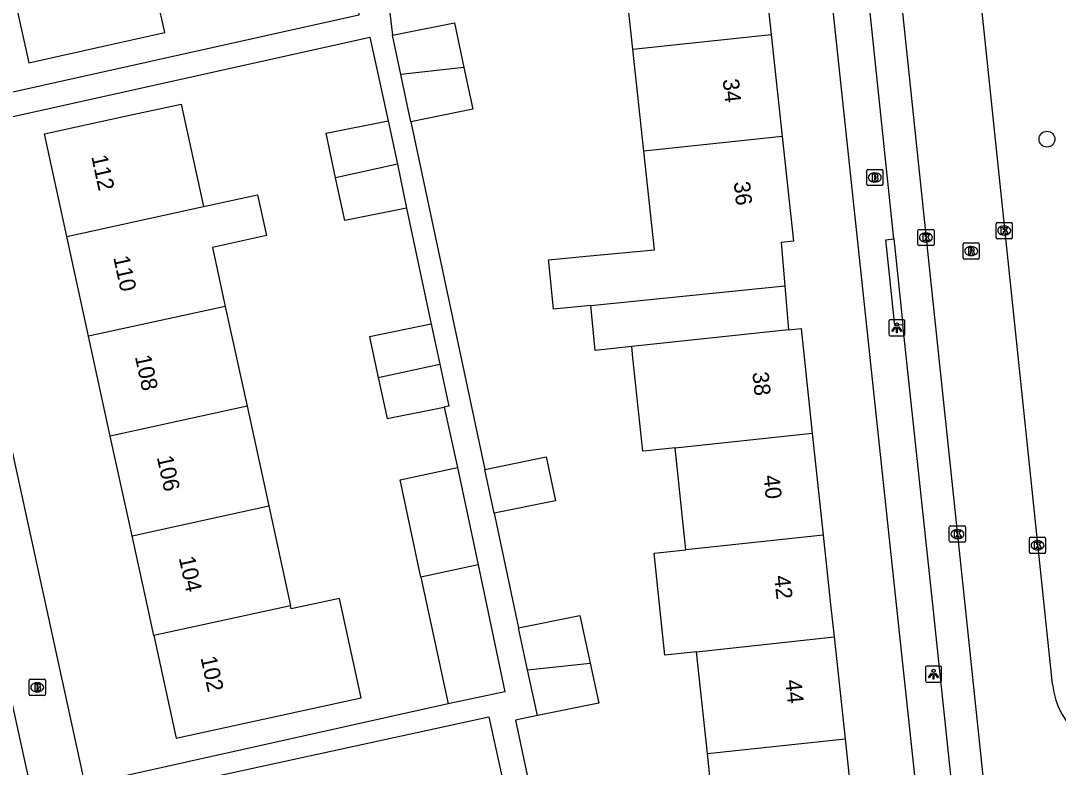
# Model space of a CAD drawing. Extents: x 160557 to 161245, y 385330 to 386505.
# Drawn here: x 160716.6 to 160780.6, y 385990 to 386036 of the extents above; entities that cross this region are included whole.
import ezdxf

# ---------------------------------------------------------------- set-up
doc = ezdxf.new("R2010")
doc.units = 0
for name, color, linetype in [('IMGEO_Boom', 7, 'Continuous'), ('IMGEO_Brandkraan', 7, 'Continuous'), ('IMGEO_Fietspad_gesloten', 7, 'Continuous'), ('IMGEO_Kolk', 7, 'Continuous'), ('IMGEO_Lichtpunt', 7, 'Continuous'), ('IMGEO_Pand', 7, 'Continuous'), ('IMGEO_Pand_nummerreeks', 7, 'Continuous'), ('IMGEO_Rijbaan_lokaal_open', 7, 'Continuous'), ('IMGEO_Rioolput', 7, 'Continuous'), ('IMGEO_Voetpad_open', 7, 'Continuous')]:
    doc.layers.add(name, color=color, linetype=linetype)

msp = doc.modelspace()

# ---------------------------------------------------------------- linework, layer by layer
at = {"layer": 'IMGEO_Boom'}
msp.add_circle((160779.939, 386028.694), 0.489, dxfattribs=at)
at = {"layer": 'IMGEO_Brandkraan'}
for p, q in [((160768.892, 386026.835), (160769.744, 386026.835)), ((160768.817, 386025.909), (160768.817, 386026.761)), ((160769.305, 386026.615), (160769.33, 386026.615)), ((160769.818, 386026.761), (160769.818, 386025.909)), ((160769.744, 386025.835), (160768.892, 386025.835)), ((160769.328, 386026.055), (160769.303, 386026.055)), ((160717.141, 385994.464), (160717.141, 385995.316)), ((160717.216, 385995.39), (160718.068, 385995.39)), ((160717.629, 385995.17), (160717.654, 385995.17)), ((160718.142, 385995.316), (160718.142, 385994.464)), ((160718.068, 385994.39), (160717.216, 385994.39)), ((160717.652, 385994.61), (160717.627, 385994.61))]:
    msp.add_line(p, q, dxfattribs=at)
for points in [[(160768.892, 386026.835), (160769.744, 386026.835)], [(160768.817, 386025.909), (160768.817, 386026.761)], [(160769.165, 386026.535), (160769.165, 386026.135), (160769.378, 386026.135)], [(160769.396, 386026.535), (160769.165, 386026.535)], [(160769.344, 386026.454), (160769.29, 386026.454), (160769.29, 386026.378)], [(160769.29, 386026.378), (160769.343, 386026.378)], [(160769.352, 386026.302), (160769.29, 386026.302), (160769.29, 386026.221)], [(160769.29, 386026.221), (160769.352, 386026.221)], [(160769.818, 386026.761), (160769.818, 386025.909)], [(160769.744, 386025.835), (160768.892, 386025.835)], [(160717.141, 385994.464), (160717.141, 385995.316)], [(160717.216, 385995.39), (160718.068, 385995.39)], [(160717.489, 385995.09), (160717.489, 385994.69), (160717.702, 385994.69)], [(160717.72, 385995.09), (160717.489, 385995.09)], [(160717.668, 385995.009), (160717.614, 385995.009), (160717.614, 385994.933)], [(160717.614, 385994.933), (160717.667, 385994.933)], [(160717.676, 385994.857), (160717.614, 385994.857), (160717.614, 385994.776)], [(160717.614, 385994.776), (160717.676, 385994.776)], [(160718.142, 385995.316), (160718.142, 385994.464)], [(160718.068, 385994.39), (160717.216, 385994.39)]]:
    msp.add_lwpolyline(points, dxfattribs=at)
for centre, radius, start, end in [((160768.894, 386026.759), 0.0765, 91.55205, 178.44795), ((160768.894, 386026.759), 0.0765, 91.55205, 178.44795), ((160769.742, 386026.759), 0.0765, 1.55205, 88.44795), ((160769.742, 386026.759), 0.0765, 1.55205, 88.44795), ((160769.345, 386026.416), 0.0379, 267.82845, 90.93552), ((160769.353, 386026.261), 0.0404, 269.87594, 90.50774), ((160769.384, 386026.386), 0.251, 268.66757, 293.53466), ((160769.4, 386026.39), 0.145, 59.4692, 91.53667), ((160769.425, 386026.437), 0.0922, 285.51372, 58.15012), ((160769.43, 386026.245), 0.105, 301.31148, 78.98903), ((160768.894, 386025.911), 0.0765, 181.55205, 268.44795), ((160768.894, 386025.911), 0.0765, 181.55205, 268.44795), ((160769.742, 386025.911), 0.0765, 271.55205, 358.44795), ((160769.742, 386025.911), 0.0765, 271.55205, 358.44795), ((160717.218, 385995.314), 0.0765, 91.55205, 178.44795), ((160717.218, 385995.314), 0.0765, 91.55205, 178.44795), ((160717.669, 385994.971), 0.0379, 267.82845, 90.93552), ((160717.677, 385994.816), 0.0404, 269.87594, 90.50774), ((160717.724, 385994.945), 0.145, 59.4692, 91.53667), ((160717.749, 385994.992), 0.0922, 285.51372, 58.15012), ((160717.754, 385994.8), 0.105, 301.31148, 78.98903), ((160718.066, 385995.314), 0.0765, 1.55205, 88.44795), ((160718.066, 385995.314), 0.0765, 1.55205, 88.44795), ((160717.218, 385994.466), 0.0765, 181.55205, 268.44795), ((160717.218, 385994.466), 0.0765, 181.55205, 268.44795), ((160717.708, 385994.941), 0.251, 268.66757, 293.53466), ((160718.066, 385994.466), 0.0765, 271.55205, 358.44795), ((160718.066, 385994.466), 0.0765, 271.55205, 358.44795)]:
    msp.add_arc(centre, radius, start, end, dxfattribs=at)
for centre, major_axis, ratio, start_param, end_param in [((160769.304, 386026.335), (-0.387, 0.002), 0.722429, 4.712389, 7.853982), ((160769.329, 386026.335), (-0.39, 0.002), 0.717154, 1.570796, 4.712389), ((160717.628, 385994.89), (-0.387, 0.002), 0.722429, 4.712389, 7.853982), ((160717.653, 385994.89), (-0.39, 0.002), 0.717154, 1.570796, 4.712389)]:
    msp.add_ellipse(centre, major_axis=major_axis, ratio=ratio, start_param=start_param, end_param=end_param, dxfattribs=at)
at = {"layer": 'IMGEO_Fietspad_gesloten'}
msp.add_lwpolyline([(160734.335, 385910.619), (160688.379, 386120.515), (160685.475, 386134.246), (160684.879, 386136.929)], dxfattribs=at)
at = {"layer": 'IMGEO_Kolk'}
for p, q in [((160771.972, 386022.203), (160771.972, 386023.055)), ((160772.047, 386023.129), (160772.899, 386023.129)), ((160772.973, 386023.055), (160772.973, 386022.203)), ((160776.803, 386022.632), (160776.803, 386023.484)), ((160776.878, 386023.558), (160777.73, 386023.558)), ((160777.291, 386023.338), (160777.316, 386023.338)), ((160777.804, 386023.484), (160777.804, 386022.632)), ((160772.483, 386022.349), (160772.458, 386022.349)), ((160772.46, 386022.909), (160772.485, 386022.909)), ((160777.73, 386022.558), (160776.878, 386022.558)), ((160777.314, 386022.778), (160777.289, 386022.778)), ((160772.899, 386022.129), (160772.047, 386022.129)), ((160773.917, 386003.915), (160773.917, 386004.767)), ((160773.992, 386004.841), (160774.844, 386004.841)), ((160774.405, 386004.621), (160774.43, 386004.621)), ((160774.918, 386004.767), (160774.918, 386003.915)), ((160774.844, 386003.841), (160773.992, 386003.841)), ((160774.428, 386004.061), (160774.403, 386004.061)), ((160778.859, 386003.22), (160778.859, 386004.072)), ((160778.934, 386004.146), (160779.786, 386004.146)), ((160779.347, 386003.926), (160779.372, 386003.926)), ((160779.86, 386004.072), (160779.86, 386003.22)), ((160779.786, 386003.146), (160778.934, 386003.146)), ((160779.37, 386003.366), (160779.345, 386003.366))]:
    msp.add_line(p, q, dxfattribs=at)
for points in [[(160771.972, 386022.203), (160771.972, 386023.055)], [(160772.047, 386023.129), (160772.899, 386023.129)], [(160772.973, 386023.055), (160772.973, 386022.203)], [(160776.803, 386022.632), (160776.803, 386023.484)], [(160776.878, 386023.558), (160777.73, 386023.558)], [(160777.124, 386023.258), (160777.247, 386023.258), (160777.247, 386023.107), (160777.377, 386023.258), (160777.541, 386023.258), (160777.395, 386023.107), (160777.548, 386022.858), (160777.396, 386022.858), (160777.311, 386023.022), (160777.247, 386022.955), (160777.247, 386022.858), (160777.124, 386022.858), (160777.124, 386023.258)], [(160777.804, 386023.484), (160777.804, 386022.632)], [(160772.293, 386022.829), (160772.416, 386022.829), (160772.416, 386022.678), (160772.546, 386022.829), (160772.71, 386022.829), (160772.564, 386022.678), (160772.717, 386022.429), (160772.565, 386022.429), (160772.48, 386022.593), (160772.416, 386022.526), (160772.416, 386022.429), (160772.293, 386022.429), (160772.293, 386022.829)], [(160777.73, 386022.558), (160776.878, 386022.558)], [(160772.899, 386022.129), (160772.047, 386022.129)], [(160773.917, 386003.915), (160773.917, 386004.767)], [(160773.992, 386004.841), (160774.844, 386004.841)], [(160774.238, 386004.541), (160774.361, 386004.541), (160774.361, 386004.39), (160774.491, 386004.541), (160774.655, 386004.541), (160774.509, 386004.39), (160774.662, 386004.141), (160774.51, 386004.141), (160774.425, 386004.305), (160774.361, 386004.238), (160774.361, 386004.141), (160774.238, 386004.141), (160774.238, 386004.541)], [(160774.918, 386004.767), (160774.918, 386003.915)], [(160774.844, 386003.841), (160773.992, 386003.841)], [(160778.859, 386003.22), (160778.859, 386004.072)], [(160778.934, 386004.146), (160779.786, 386004.146)], [(160779.18, 386003.846), (160779.303, 386003.846), (160779.303, 386003.695), (160779.433, 386003.846), (160779.597, 386003.846), (160779.451, 386003.695), (160779.604, 386003.446), (160779.452, 386003.446), (160779.367, 386003.61), (160779.303, 386003.543), (160779.303, 386003.446), (160779.18, 386003.446), (160779.18, 386003.846)], [(160779.86, 386004.072), (160779.86, 386003.22)], [(160779.786, 386003.146), (160778.934, 386003.146)]]:
    msp.add_lwpolyline(points, dxfattribs=at)
for centre, start, end in [((160772.049, 386023.053), 91.55205, 178.44795), ((160772.049, 386023.053), 91.55205, 178.44795), ((160772.897, 386023.053), 1.55205, 88.44795), ((160772.897, 386023.053), 1.55205, 88.44795), ((160776.88, 386023.482), 91.55205, 178.44795), ((160776.88, 386023.482), 91.55205, 178.44795), ((160777.728, 386023.482), 1.55205, 88.44795), ((160777.728, 386023.482), 1.55205, 88.44795), ((160776.88, 386022.634), 181.55205, 268.44795), ((160776.88, 386022.634), 181.55205, 268.44795), ((160777.728, 386022.634), 271.55205, 358.44795), ((160777.728, 386022.634), 271.55205, 358.44795), ((160772.049, 386022.205), 181.55205, 268.44795), ((160772.049, 386022.205), 181.55205, 268.44795), ((160772.897, 386022.205), 271.55205, 358.44795), ((160772.897, 386022.205), 271.55205, 358.44795), ((160773.994, 386004.765), 91.55205, 178.44795), ((160773.994, 386004.765), 91.55205, 178.44795), ((160774.842, 386004.765), 1.55205, 88.44795), ((160774.842, 386004.765), 1.55205, 88.44795), ((160773.994, 386003.917), 181.55205, 268.44795), ((160773.994, 386003.917), 181.55205, 268.44795), ((160774.842, 386003.917), 271.55205, 358.44795), ((160774.842, 386003.917), 271.55205, 358.44795), ((160778.936, 386004.07), 91.55205, 178.44795), ((160778.936, 386004.07), 91.55205, 178.44795), ((160779.784, 386004.07), 1.55205, 88.44795), ((160779.784, 386004.07), 1.55205, 88.44795), ((160778.936, 386003.222), 181.55205, 268.44795), ((160778.936, 386003.222), 181.55205, 268.44795), ((160779.784, 386003.222), 271.55205, 358.44795), ((160779.784, 386003.222), 271.55205, 358.44795)]:
    msp.add_arc(centre, 0.0765, start, end, dxfattribs=at)
for centre, major_axis, ratio, start_param, end_param in [((160777.29, 386023.058), (-0.387, 0.002), 0.722429, 4.712389, 7.853982), ((160777.315, 386023.058), (-0.39, 0.002), 0.717154, 1.570796, 4.712389), ((160772.459, 386022.629), (-0.387, 0.002), 0.722429, 4.712389, 7.853982), ((160772.484, 386022.629), (-0.39, 0.002), 0.717154, 1.570796, 4.712389), ((160774.404, 386004.341), (-0.387, 0.002), 0.722429, 4.712389, 7.853982), ((160774.429, 386004.341), (-0.39, 0.002), 0.717154, 1.570796, 4.712389), ((160779.346, 386003.646), (-0.387, 0.002), 0.722429, 4.712389, 7.853982), ((160779.371, 386003.646), (-0.39, 0.002), 0.717154, 1.570796, 4.712389)]:
    msp.add_ellipse(centre, major_axis=major_axis, ratio=ratio, start_param=start_param, end_param=end_param, dxfattribs=at)
at = {"layer": 'IMGEO_Lichtpunt'}
for p, q in [((160770.18, 386017.468), (160770.18, 386016.661)), ((160770.18, 386017.468), (160770.18, 386016.661)), ((160771.082, 386017.563), (160770.274, 386017.563)), ((160771.082, 386017.563), (160770.274, 386017.563)), ((160771.176, 386016.661), (160771.176, 386017.468)), ((160771.176, 386016.661), (160771.176, 386017.468)), ((160770.274, 386016.567), (160771.082, 386016.567)), ((160770.274, 386016.567), (160771.082, 386016.567)), ((160772.444, 385996.107), (160772.444, 385995.3)), ((160772.444, 385996.107), (160772.444, 385995.3)), ((160773.346, 385996.202), (160772.538, 385996.202)), ((160773.346, 385996.202), (160772.538, 385996.202)), ((160773.44, 385995.3), (160773.44, 385996.107)), ((160773.44, 385995.3), (160773.44, 385996.107)), ((160772.538, 385995.206), (160773.346, 385995.206)), ((160772.538, 385995.206), (160773.346, 385995.206))]:
    msp.add_line(p, q, dxfattribs=at)
for points in [[(160770.554, 386017.132), (160770.593, 386017.104), (160770.405, 386016.842), (160770.367, 386016.869), (160770.554, 386017.132)], [(160770.656, 386017.084), (160770.703, 386017.084), (160770.703, 386016.762), (160770.656, 386016.762), (160770.656, 386017.084)], [(160770.766, 386017.104), (160770.804, 386017.131), (160770.991, 386016.869), (160770.952, 386016.841), (160770.766, 386017.104)], [(160772.818, 385995.771), (160772.857, 385995.743), (160772.669, 385995.481), (160772.631, 385995.508), (160772.818, 385995.771)], [(160772.92, 385995.723), (160772.967, 385995.723), (160772.967, 385995.401), (160772.92, 385995.401), (160772.92, 385995.723)], [(160773.03, 385995.743), (160773.068, 385995.77), (160773.255, 385995.508), (160773.216, 385995.48), (160773.03, 385995.743)]]:
    msp.add_lwpolyline(points, dxfattribs=at)
for centre in [(160770.679, 386017.266), (160772.943, 385995.905)]:
    msp.add_circle(centre, 0.0994, dxfattribs=at)
for centre, start, end in [((160770.274, 386017.468), 90, 180), ((160770.274, 386017.468), 90, 180), ((160771.082, 386017.468), 0, 90), ((160771.082, 386017.468), 0, 90), ((160770.274, 386016.661), 180, 270), ((160770.274, 386016.661), 180, 270), ((160771.082, 386016.661), 270, 0), ((160771.082, 386016.661), 270, 360), ((160772.538, 385996.107), 90, 180), ((160772.538, 385996.107), 90, 180), ((160773.346, 385996.107), 0, 90), ((160773.346, 385996.107), 0, 90), ((160772.538, 385995.3), 180, 270), ((160772.538, 385995.3), 180, 270), ((160773.346, 385995.3), 270, 0), ((160773.346, 385995.3), 270, 360)]:
    msp.add_arc(centre, 0.0946, start, end, dxfattribs=at)
at = {"layer": 'IMGEO_Pand'}
for points in [[(160715.715, 386039.709), (160717.125, 386033.397), (160722.005, 386034.487), (160725.508, 386035.269), (160724.098, 386041.582)], [(160762.249, 386041.449), (160762.929, 386035.159)], [(160754.388, 386034.237), (160753.708, 386040.527)], [(160739.558, 386035.103), (160743.383, 386035.875), (160743.968, 386033.112)], [(160740.071, 386032.691), (160739.558, 386035.103)], [(160754.388, 386034.237), (160762.929, 386035.159)], [(160762.929, 386035.159), (160763.608, 386028.868)], [(160755.067, 386027.946), (160754.388, 386034.237)], [(160743.968, 386033.112), (160740.071, 386032.691)], [(160740.693, 386029.77), (160740.071, 386032.691)], [(160743.968, 386033.112), (160744.512, 386030.541), (160740.693, 386029.77)], [(160719.465, 386022.696), (160718.086, 386029.02), (160722.972, 386030.085), (160726.52, 386030.859), (160727.899, 386024.536)], [(160736.049, 386026.314), (160735.462, 386029.059), (160739.291, 386029.832)], [(160739.291, 386029.832), (160739.861, 386027.146)], [(160763.608, 386028.868), (160755.067, 386027.946)], [(160763.608, 386028.868), (160764.306, 386022.407), (160763.531, 386022.324), (160763.76, 386019.649)], [(160751.8, 386018.44), (160749.503, 386018.208), (160749.208, 386021.121), (160749.194, 386021.26), (160751.518, 386021.476), (160755.723, 386021.867), (160755.067, 386027.946)], [(160739.861, 386027.146), (160736.049, 386026.314)], [(160739.861, 386027.146), (160740.433, 386024.45)], [(160740.433, 386024.45), (160736.612, 386023.679), (160736.049, 386026.314)], [(160727.899, 386024.536), (160731.238, 386025.264), (160731.786, 386022.751), (160728.447, 386022.023), (160729.241, 386018.382)], [(160719.465, 386022.696), (160727.899, 386024.536)], [(160720.808, 386016.542), (160719.465, 386022.696)], [(160751.8, 386018.44), (160763.76, 386019.649)], [(160763.76, 386019.649), (160763.992, 386016.94)], [(160729.241, 386018.382), (160720.808, 386016.542)], [(160729.241, 386018.382), (160730.584, 386012.228)], [(160754.318, 386015.905), (160752.058, 386015.663), (160751.8, 386018.44)], [(160741.955, 386017.283), (160738.143, 386016.513), (160738.682, 386013.994)], [(160741.955, 386017.283), (160742.477, 386014.822)], [(160722.15, 386010.388), (160720.808, 386016.542)], [(160763.992, 386016.94), (160754.318, 386015.905)], [(160763.992, 386016.94), (160764.767, 386017.023), (160765.459, 386010.565)], [(160757.007, 386009.659), (160755.246, 386009.471), (160755.008, 386009.446), (160754.393, 386015.205), (160754.342, 386015.677), (160754.318, 386015.905)], [(160738.682, 386013.994), (160742.477, 386014.822)], [(160742.477, 386014.822), (160743.027, 386012.231), (160742.739, 386012.173)], [(160738.682, 386013.994), (160739.223, 386011.463), (160742.739, 386012.173)], [(160730.584, 386012.228), (160722.15, 386010.388)], [(160730.584, 386012.228), (160731.926, 386006.073)], [(160723.493, 386004.233), (160722.15, 386010.388)], [(160757.007, 386009.659), (160765.459, 386010.565)], [(160765.459, 386010.565), (160766.132, 386004.28)], [(160757.667, 386003.373), (160757.007, 386009.659)], [(160745.257, 386008.332), (160749.046, 386009.097), (160749.618, 386006.396), (160745.832, 386005.631)], [(160741.315, 386001.674), (160740.032, 386007.683), (160743.567, 386008.438)], [(160743.567, 386008.438), (160744.838, 386002.443)], [(160745.832, 386005.631), (160745.257, 386008.332)], [(160723.493, 386004.233), (160731.926, 386006.073)], [(160731.926, 386006.073), (160733.269, 385999.919)], [(160724.835, 385998.079), (160724.416, 386000), (160723.493, 386004.233)], [(160766.132, 386004.28), (160757.667, 386003.373)], [(160766.132, 386004.28), (160766.591, 386000), (160766.806, 385997.995)], [(160758.327, 385997.087), (160756.36, 385996.876), (160756.032, 386000), (160755.7, 386003.162), (160757.667, 386003.373)], [(160744.838, 386002.443), (160741.315, 386001.674)], [(160744.838, 386002.443), (160746.499, 385994.611), (160742.985, 385993.866)], [(160741.315, 386001.674), (160742.985, 385993.866)], [(160724.835, 385998.079), (160726.214, 385991.756), (160731.1, 385992.821), (160737.626, 385994.245), (160736.29, 386000.374), (160733.311, 385999.724), (160733.269, 385999.919)], [(160733.269, 385999.919), (160724.835, 385998.079)], [(160747.337, 385998.56), (160751.114, 385999.323), (160751.749, 385996.382)], [(160747.896, 385995.969), (160747.337, 385998.56)], [(160758.327, 385997.087), (160766.806, 385997.995)], [(160766.806, 385997.995), (160767.48, 385991.709)], [(160758.987, 385990.799), (160758.327, 385997.087)], [(160747.896, 385995.969), (160751.749, 385996.382)], [(160751.749, 385996.382), (160752.283, 385993.906), (160748.505, 385993.143)], [(160748.505, 385993.143), (160747.896, 385995.969)], [(160758.987, 385990.799), (160767.48, 385991.709)], [(160767.48, 385991.709), (160768.153, 385985.424)], [(160756.488, 385984.174), (160756.186, 385986.993), (160759.352, 385987.332), (160758.987, 385990.799)]]:
    msp.add_lwpolyline(points, dxfattribs=at)
at = {"layer": 'IMGEO_Rijbaan_lokaal_open'}
for points in [[(160767.112, 386073.774), (160772.645, 386021.005), (160774.881, 386000), (160776.471, 385984.724)], [(160780.285, 385995.082), (160779.77, 386000), (160775.425, 386041.464)]]:
    msp.add_lwpolyline(points, dxfattribs=at)
msp.add_arc((160785.19, 385995.612), 4.934, 186.17186, 275.90952, dxfattribs=at)
at = {"layer": 'IMGEO_Rioolput'}
for p, q in [((160774.84, 386022.296), (160775.692, 386022.296)), ((160774.765, 386021.37), (160774.765, 386022.222)), ((160775.253, 386022.076), (160775.278, 386022.076)), ((160775.766, 386022.222), (160775.766, 386021.37)), ((160775.692, 386021.296), (160774.84, 386021.296)), ((160775.276, 386021.516), (160775.251, 386021.516))]:
    msp.add_line(p, q, dxfattribs=at)
for points in [[(160774.84, 386022.296), (160775.692, 386022.296)], [(160774.765, 386021.37), (160774.765, 386022.222)], [(160775.354, 386021.994), (160775.102, 386021.996), (160775.102, 386021.596)], [(160775.102, 386021.596), (160775.226, 386021.596), (160775.226, 386021.758), (160775.237, 386021.758)], [(160775.28, 386021.915), (160775.226, 386021.915), (160775.226, 386021.834)], [(160775.226, 386021.834), (160775.278, 386021.834)], [(160775.284, 386021.729), (160775.355, 386021.596), (160775.495, 386021.596), (160775.43, 386021.722)], [(160775.766, 386022.222), (160775.766, 386021.37)], [(160775.692, 386021.296), (160774.84, 386021.296)]]:
    msp.add_lwpolyline(points, dxfattribs=at)
for centre, radius, start, end in [((160774.842, 386022.22), 0.0765, 91.55205, 178.44795), ((160774.842, 386022.22), 0.0765, 91.55205, 178.44795), ((160775.69, 386022.22), 0.0765, 1.55205, 88.44795), ((160775.69, 386022.22), 0.0765, 1.55205, 88.44795), ((160775.236, 386021.705), 0.0533, 26.02933, 88.69889), ((160775.262, 386022.023), 0.19, 274.7715, 282.96867), ((160775.286, 386021.819), 0.0964, 77.00612, 93.18647), ((160775.3, 386021.876), 0.0378, 276.66336, 79.67722), ((160775.353, 386021.884), 0.109, 350.36119, 89.41601), ((160775.351, 386021.884), 0.112, 277.58423, 350.98172), ((160775.335, 386021.669), 0.108, 29.51342, 73.79051), ((160774.842, 386021.372), 0.0765, 181.55205, 268.44795), ((160774.842, 386021.372), 0.0765, 181.55205, 268.44795), ((160775.69, 386021.372), 0.0765, 271.55205, 358.44795), ((160775.69, 386021.372), 0.0765, 271.55205, 358.44795)]:
    msp.add_arc(centre, radius, start, end, dxfattribs=at)
for centre, major_axis, ratio, start_param, end_param in [((160775.252, 386021.796), (-0.387, 0.002), 0.722429, 4.712389, 7.853982), ((160775.277, 386021.796), (-0.39, 0.002), 0.717154, 1.570796, 4.712389)]:
    msp.add_ellipse(centre, major_axis=major_axis, ratio=ratio, start_param=start_param, end_param=end_param, dxfattribs=at)
at = {"layer": 'IMGEO_Voetpad_open'}
for points in [[(160772.629, 385971.543), (160773.674, 385971.815), (160770.665, 386000), (160762.861, 386073.091)], [(160770.498, 386022.549), (160765.519, 386070.113)], [(160738.564, 386042.902), (160739.222, 386037.889), (160739.558, 386035.103)], [(160737.025, 386041.21), (160737.484, 386036.351), (160711.403, 386030.553)], [(160711.783, 386029.121), (160738.155, 386034.996), (160739.291, 386029.832)], [(160740.693, 386029.77), (160745.257, 386008.332)], [(160711.783, 386029.121), (160711.803, 386029.046), (160720.571, 385988.884)], [(160740.433, 386024.45), (160741.955, 386017.283)], [(160771.058, 386017.254), (160770.561, 386017.202), (160770.001, 386022.497), (160770.498, 386022.549)], [(160770.498, 386022.549), (160770.681, 386020.798), (160771.058, 386017.254)], [(160774.286, 385986.931), (160772.895, 386000), (160771.058, 386017.254)], [(160742.739, 386012.173), (160743.567, 386008.438)], [(160745.832, 386005.631), (160747.031, 386000), (160747.337, 385998.56)], [(160742.985, 385993.866), (160720.571, 385988.884)], [(160720.831, 385987.697), (160745.506, 385993.063), (160746.648, 385987.811)], [(160748.505, 385993.143), (160747.152, 385992.864), (160748.663, 385985.688)]]:
    msp.add_lwpolyline(points, dxfattribs=at)

# ---------------------------------------------------------------- texts
at = {"layer": 'IMGEO_Pand_nummerreeks'}
for s, rotation, p in [('34', 276.16501, (160759.93, 386032.377)), ('112', 282.30529, (160720.971, 386027.624)), ('36', 276.16482, (160760.614, 386026.043)), ('110', 282.30529, (160722.326, 386021.408)), ('108', 282.30529, (160723.662, 386015.286)), ('38', 276.11325, (160761.759, 386014.305)), ('106', 282.30529, (160725.015, 386009.08)), ('40', 276.11586, (160762.443, 386007.935)), ('104', 282.30529, (160726.37, 386002.87)), ('42', 276.12471, (160763.105, 386001.751)), ('102', 282.30119, (160727.711, 385996.714)), ('44', 276.1178, (160763.793, 385995.324))]:
    msp.add_text(s, height=1, rotation=rotation, dxfattribs=at).set_placement(p)

doc.saveas('drawing.dxf')
